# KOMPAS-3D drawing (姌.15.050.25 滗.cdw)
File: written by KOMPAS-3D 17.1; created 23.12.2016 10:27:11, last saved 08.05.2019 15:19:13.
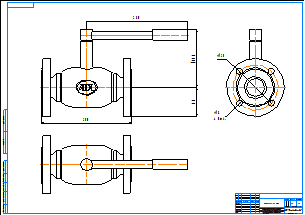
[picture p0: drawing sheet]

Sheet 1: A1, landscape

Title block, sheet 1: name: КШ.15.050.25 фф; material: Внимание! Данный продукт является объектом авторского права ООО «Торговый Дом АДЛ». / Запрещается изменение, копирование, распространение / (в том числе путем копирования на другие сайты и ресурсы в Интернете) / или любое иное использование информации и объектов без предварительного / согласия правообладателя (ООО «Торговый Дом АДЛ»).; mass: 1,3; sheets: 1; organisation: ООО "Торговый дом АДЛ"; sheet format: A1; stored path: C:\Users\tra\Desktop\2д чертежи\Шаровые краны БИВАЛ\КШ_Бивал_серия_14_15\KOMPAS_2D\КШ.15.050.25 фф.cdw

Views: Вид 1, Проекционный вид 2, Проекционный вид 3
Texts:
  Klimkovich
  ADL
Dimensions and other numbers on the sheet: 250; 280; 159,3; 80; 125; 18; 4 Отв.; 1:1; 1; 1,3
